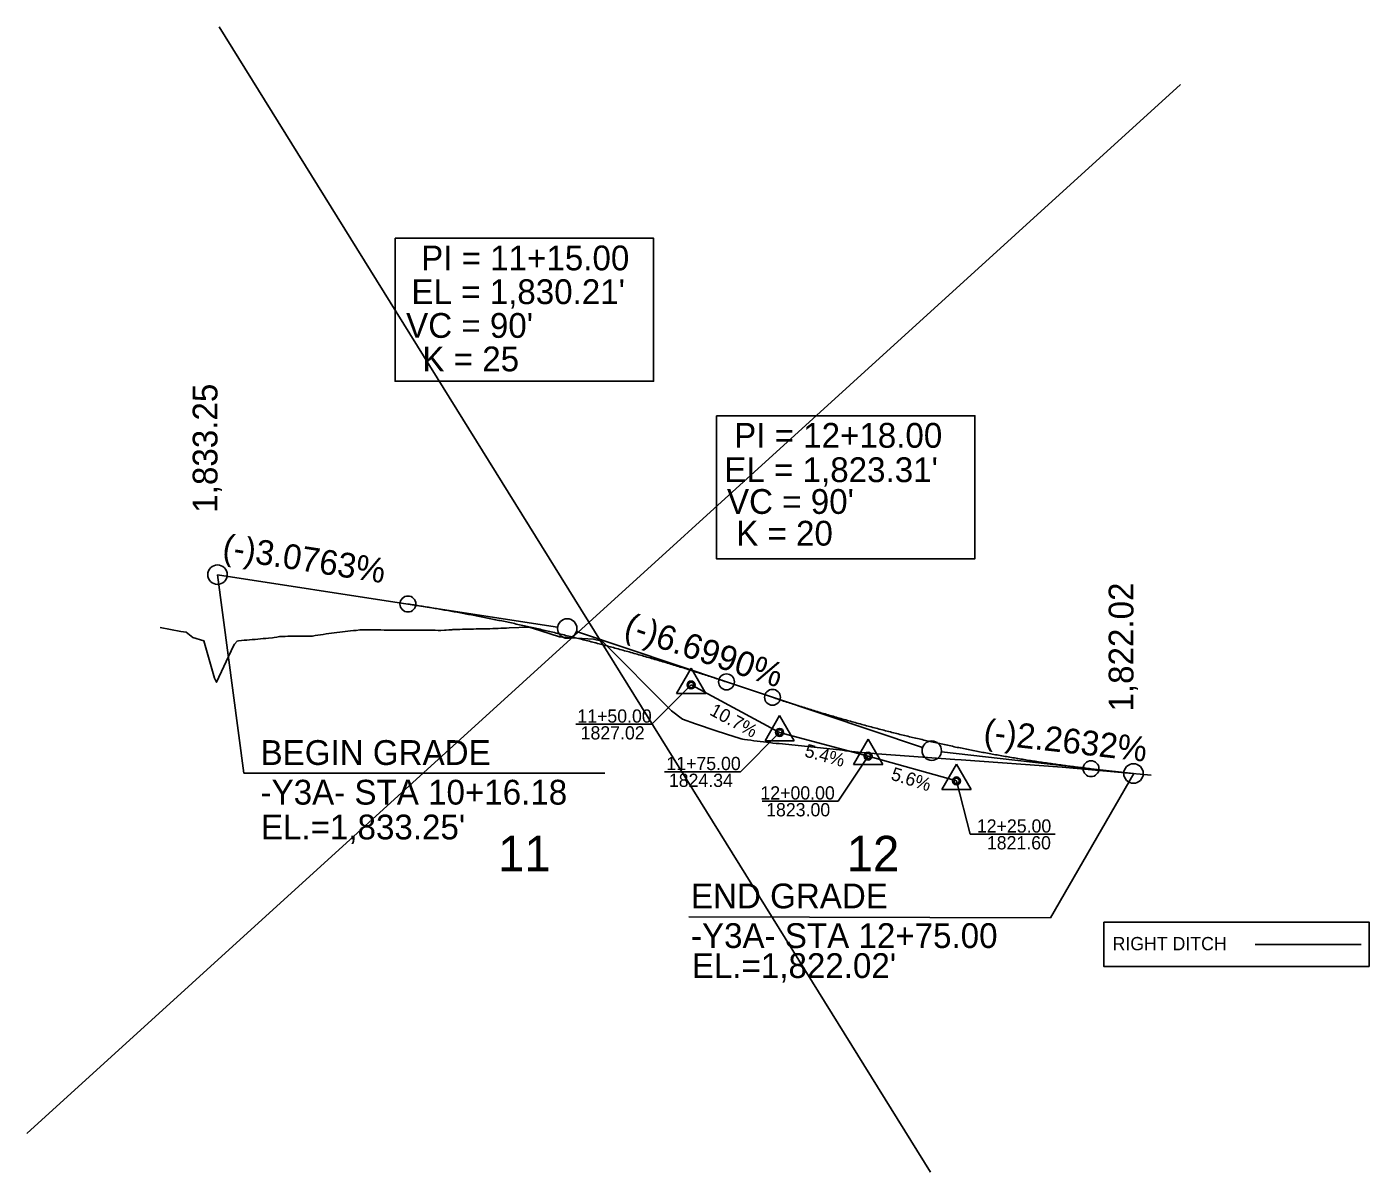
# Model space of a CAD drawing. Extents: x 557032 to 558930, y 525869 to 527437.
# Drawn here: x 557603.4 to 557982.7, y 527113.6 to 527437.1 of the extents above; entities that cross this region are included whole.
import ezdxf

# ---------------------------------------------------------------- set-up
doc = ezdxf.new("R2010")
doc.units = 0
for name, color, linetype in [('Exist Vertical Profile Ground Line', 7, 'Continuous'), ('Exist Vertical Profile Horizontal Axis Label Major', 7, 'Continuous'), ('Prop Grid Mask', 7, 'Continuous'), ('Prop PFL Ditch Label CELL', 7, 'Continuous'), ('Prop PFL VPI Symbol CELL', 7, 'Continuous'), ('Prop Vertical Profile Curve Label', 7, 'Continuous'), ('Prop Vertical Profile Grade', 7, 'Continuous'), ('Prop Vertical Profile Grade Label', 7, 'Continuous'), ('Prop VPI Label', 7, 'Continuous')]:
    doc.layers.add(name, color=color, linetype=linetype)

msp = doc.modelspace()

# ---------------------------------------------------------------- linework, layer by layer
at = {"layer": 'Exist Vertical Profile Ground Line'}
for points in [[(557641.09, 527267.42), (557646.95, 527266.33), (557648.42, 527266.09), (557650.28, 527264.59), (557653.44, 527263.67), (557656.4, 527253.1), (557657.02, 527251.96), (557661.78, 527262.29), (557662.12, 527262.74), (557662.81, 527263.59), (557663.24, 527263.64), (557664.01, 527263.73), (557664.79, 527263.8), (557665.56, 527263.87), (557666.33, 527263.94), (557667.1, 527264.01), (557667.87, 527264.08), (557668.65, 527264.15), (557669.42, 527264.21), (557670.19, 527264.28), (557670.96, 527264.34), (557671.73, 527264.4), (557672.77, 527264.48), (557673.28, 527264.57), (557674.05, 527264.7), (557674.82, 527264.84), (557675.2, 527264.9), (557675.59, 527264.91), (557676.36, 527264.92), (557677.14, 527264.93), (557677.91, 527264.94), (557678.68, 527264.94), (557679.45, 527264.95), (557680.22, 527264.96), (557681, 527264.97), (557681.4, 527264.97), (557681.77, 527264.97), (557682.54, 527264.96), (557683.31, 527264.96), (557683.62, 527264.96), (557684.08, 527264.99), (557684.85, 527265.16), (557685.63, 527265.27), (557686.4, 527265.38), (557687.17, 527265.48), (557687.94, 527265.59), (557688.71, 527265.69), (557689.49, 527265.79), (557690.26, 527265.89), (557691.03, 527265.99), (557691.8, 527266.08), (557692.57, 527266.18), (557693.35, 527266.27), (557694.12, 527266.36), (557694.89, 527266.45), (557695.66, 527266.54), (557696.43, 527266.62), (557697.49, 527266.74), (557697.98, 527266.74), (557698.75, 527266.74), (557699.52, 527266.73), (557700.29, 527266.73), (557701.06, 527266.73), (557701.84, 527266.72), (557702.61, 527266.72), (557703.38, 527266.72), (557704.4, 527266.71), (557704.92, 527266.71), (557705.7, 527266.71), (557706.47, 527266.71), (557707.24, 527266.71), (557708.01, 527266.71), (557708.78, 527266.71), (557709.55, 527266.7), (557710.33, 527266.7), (557711.1, 527266.7), (557711.87, 527266.7), (557712.64, 527266.69), (557713.41, 527266.69), (557714.19, 527266.69), (557714.96, 527266.68), (557715.73, 527266.68), (557716.5, 527266.68), (557717.27, 527266.67), (557718.05, 527266.67), (557718.51, 527266.66), (557718.82, 527266.64), (557719.59, 527266.6), (557720.36, 527266.59), (557721.39, 527266.65), (557721.9, 527266.69), (557722.68, 527266.75), (557723.45, 527266.81), (557723.78, 527266.84), (557724.22, 527266.85), (557724.99, 527266.88), (557725.76, 527266.9), (557726.54, 527266.92), (557727.31, 527266.94), (557728.08, 527266.96), (557728.85, 527266.98)], [(557728.85, 527266.98), (557729.62, 527267), (557730.39, 527267.02), (557731.17, 527267.03), (557731.94, 527267.05), (557732.71, 527267.06), (557733.48, 527267.08), (557734.25, 527267.09), (557735.04, 527267.1), (557735.8, 527267.13), (557736.57, 527267.17), (557737.34, 527267.2), (557738.11, 527267.24), (557738.89, 527267.27), (557739.66, 527267.3), (557745.22, 527267.52), (557745.9, 527267.35), (557746.29, 527267.24), (557753.92, 527264.77), (557757.25, 527264.47), (557763.56, 527264.17), (557765.51, 527263.7), (557765.84, 527263.67), (557785.59, 527243.9), (557788.71, 527241.52), (557792.33, 527240.19), (557798.13, 527238.24), (557799.02, 527237.94), (557799.92, 527237.64), (557800.81, 527237.36), (557801.7, 527237.07), (557802.6, 527236.79), (557803.49, 527236.52), (557804.39, 527236.26), (557805.28, 527235.99), (557805.71, 527235.87), (557806.17, 527235.81), (557807.07, 527235.69), (557807.96, 527235.58), (557808.85, 527235.46), (557809.75, 527235.35), (557810.64, 527235.24), (557811.53, 527235.12), (557812.43, 527235.01), (557813.32, 527234.9), (557814.21, 527234.79), (557815.11, 527234.71), (557816, 527234.63), (557816.89, 527234.54), (557817.79, 527234.46), (557818.68, 527234.38), (557819.57, 527234.29), (557820.47, 527234.21), (557821.36, 527234.12), (557822.26, 527234.03), (557823.15, 527233.93), (557824.04, 527233.83), (557824.94, 527233.73), (557825.83, 527233.63), (557826.72, 527233.53), (557827.62, 527233.44), (557828.51, 527233.34), (557829.4, 527233.24), (557830.3, 527233.14), (557831.19, 527233.04), (557832.08, 527232.94), (557832.98, 527232.84), (557833.87, 527232.74), (557834.76, 527232.64), (557835.66, 527232.54), (557836.55, 527232.44), (557837.45, 527232.34), (557838.34, 527232.24), (557839.23, 527232.14), (557840.13, 527232.04), (557840.56, 527231.99), (557841.02, 527231.96), (557841.91, 527231.9), (557842.81, 527231.84), (557843.7, 527231.77), (557865.63, 527230.19), (557867.43, 527230.07), (557895.94, 527227.95), (557921.09, 527225.74)]]:
    msp.add_lwpolyline(points, dxfattribs=at)
at = {"layer": 'Prop Grid Mask'}
msp.add_lwpolyline([(557907.68, 527184.23), (557982.68, 527184.23), (557982.68, 527171.73), (557907.68, 527171.73)], close=True, dxfattribs=at)
at = {"layer": 'Prop PFL Ditch Label CELL'}
for p, q in [((557791.09, 527251.19), (557780.04, 527240.08)), ((557791.09, 527251.19), (557816.09, 527237.79)), ((557780.04, 527240.08), (557758.55, 527240.08)), ((557816.09, 527237.79), (557805.04, 527226.68)), ((557816.09, 527237.79), (557841.09, 527231.09)), ((557841.09, 527231.09), (557832.66, 527218.37)), ((557841.09, 527231.09), (557866.09, 527224.09)), ((557805.04, 527226.68), (557783.55, 527226.68)), ((557866.09, 527224.09), (557869.91, 527209.04)), ((557832.66, 527218.37), (557811.17, 527218.37)), ((557893.99, 527209.04), (557869.91, 527209.04)), ((557907.68, 527176.73), (557907.68, 527176.73)), ((557950.46, 527177.9), (557980.46, 527177.9))]:
    msp.add_line(p, q, dxfattribs=at)
at = {"layer": 'Prop PFL VPI Symbol CELL'}
for p, q in [((557791.09, 527255.96), (557786.98, 527248.82)), ((557791.09, 527255.96), (557795.23, 527248.82)), ((557786.98, 527248.82), (557795.23, 527248.82)), ((557816.09, 527242.56), (557811.98, 527235.42)), ((557816.09, 527242.56), (557820.23, 527235.42)), ((557841.09, 527235.86), (557836.98, 527228.72)), ((557841.09, 527235.86), (557845.23, 527228.72)), ((557811.98, 527235.42), (557820.23, 527235.42)), ((557836.98, 527228.72), (557845.23, 527228.72)), ((557866.09, 527228.86), (557861.98, 527221.72)), ((557866.09, 527228.86), (557870.23, 527221.72)), ((557861.98, 527221.72), (557870.23, 527221.72))]:
    msp.add_line(p, q, dxfattribs=at)
for centre, radius in [((557791.09, 527251.19), 1.12), ((557791.09, 527251.19), 0.765), ((557816.09, 527237.79), 1.12), ((557816.09, 527237.79), 0.765), ((557841.09, 527231.09), 1.12), ((557841.09, 527231.09), 0.765), ((557866.09, 527224.09), 1.12), ((557866.09, 527224.09), 0.765)]:
    msp.add_circle(centre, radius, dxfattribs=at)
at = {"layer": 'Prop Vertical Profile Curve Label'}
for points in [[(557707.45, 527377.35), (557780.51, 527377.35), (557780.51, 527336.95), (557707.45, 527336.95)], [(557798.23, 527327.23), (557871.29, 527327.23), (557871.29, 527286.83), (557798.23, 527286.83)]]:
    msp.add_lwpolyline(points, close=True, dxfattribs=at)
for centre in [(557711.09, 527274.06), (557801.09, 527252.07), (557814.09, 527247.71), (557904.09, 527227.55)]:
    msp.add_circle(centre, 2.25, dxfattribs=at)
at = {"layer": 'Prop Vertical Profile Grade'}
for p, q in [((557657.27, 527282.34), (557711.09, 527274.06)), ((557801.09, 527252.07), (557814.09, 527247.71)), ((557904.09, 527227.55), (557916.09, 527226.19))]:
    msp.add_line(p, q, dxfattribs=at)
for points in [[(557711.09, 527274.06), (557712.89, 527273.78), (557714.69, 527273.49), (557716.49, 527273.2), (557718.29, 527272.9), (557720.09, 527272.59), (557721.89, 527272.28), (557723.69, 527271.96), (557725.49, 527271.64), (557727.29, 527271.3), (557729.09, 527270.97), (557730.89, 527270.62), (557732.69, 527270.27), (557734.49, 527269.91), (557736.29, 527269.54), (557738.09, 527269.17), (557739.89, 527268.8), (557741.69, 527268.41), (557743.49, 527268.02), (557745.29, 527267.62), (557747.09, 527267.22), (557748.89, 527266.81), (557750.69, 527266.39), (557752.49, 527265.97), (557754.29, 527265.54), (557756.09, 527265.1), (557757.89, 527264.66), (557759.69, 527264.21), (557761.49, 527263.75), (557763.29, 527263.29), (557765.09, 527262.82), (557766.89, 527262.34), (557768.69, 527261.86), (557770.49, 527261.37), (557772.29, 527260.88), (557774.09, 527260.38), (557775.89, 527259.87), (557777.69, 527259.35), (557779.49, 527258.83), (557781.29, 527258.3), (557783.09, 527257.77), (557784.89, 527257.23), (557786.69, 527256.68), (557788.49, 527256.13), (557790.29, 527255.57), (557792.09, 527255), (557793.89, 527254.42), (557795.69, 527253.84), (557797.49, 527253.26), (557799.29, 527252.67), (557801.09, 527252.07)], [(557814.09, 527247.71), (557815.89, 527247.11), (557817.69, 527246.52), (557819.49, 527245.94), (557821.29, 527245.36), (557823.09, 527244.8), (557824.89, 527244.24), (557826.69, 527243.69), (557828.49, 527243.14), (557830.29, 527242.61), (557832.09, 527242.08), (557833.89, 527241.56), (557835.69, 527241.05), (557837.49, 527240.55), (557839.29, 527240.05), (557841.09, 527239.57), (557842.89, 527239.09), (557844.69, 527238.62), (557846.49, 527238.15), (557848.29, 527237.7), (557850.09, 527237.25), (557851.89, 527236.81), (557853.69, 527236.38), (557855.49, 527235.96), (557857.29, 527235.54), (557859.09, 527235.13), (557860.89, 527234.73), (557862.69, 527234.34), (557864.49, 527233.96), (557866.29, 527233.58), (557868.09, 527233.22), (557869.89, 527232.86), (557871.69, 527232.51), (557873.49, 527232.16), (557875.29, 527231.83), (557877.09, 527231.5), (557878.89, 527231.18), (557880.69, 527230.87), (557882.49, 527230.57), (557884.29, 527230.27), (557886.09, 527229.98), (557887.89, 527229.7), (557889.69, 527229.43), (557891.49, 527229.17), (557893.29, 527228.91), (557895.09, 527228.66), (557896.89, 527228.42), (557898.69, 527228.19), (557900.49, 527227.97), (557902.29, 527227.75), (557904.09, 527227.55)]]:
    msp.add_spline(points, degree=3, dxfattribs=at)
at = {"layer": 'Prop VPI Label'}
for p, q in [((557858.73, 527113.61), (557657.73, 527437.05)), ((557603.4, 527124.48), (557929.35, 527420.74)), ((557664.72, 527226.24), (557657.27, 527282.34)), ((557711.09, 527274.06), (557753.38, 527267.56)), ((557801.09, 527252.07), (557758.7, 527266.26)), ((557814.09, 527247.71), (557856.49, 527233.51)), ((557904.09, 527227.55), (557861.83, 527232.33)), ((557766.76, 527226.24), (557664.72, 527226.24)), ((557892.67, 527185.43), (557916.18, 527226.18)), ((557790.46, 527185.76), (557892.67, 527185.43))]:
    msp.add_line(p, q, dxfattribs=at)
for points in [[(557707.45, 527377.35), (557780.51, 527377.35), (557780.51, 527336.95), (557707.45, 527336.95)], [(557798.23, 527327.23), (557871.29, 527327.23), (557871.29, 527286.83), (557798.23, 527286.83)], [(557907.68, 527184.23), (557982.68, 527184.23), (557982.68, 527171.73), (557907.68, 527171.73)]]:
    msp.add_lwpolyline(points, close=True, dxfattribs=at)
for centre in [(557657.27, 527282.34), (557657.27, 527282.34), (557756.09, 527267.14), (557859.09, 527232.64), (557916.09, 527226.19), (557916.09, 527226.19)]:
    msp.add_circle(centre, 2.75, dxfattribs=at)

# ---------------------------------------------------------------- texts
at = {"layer": 'Exist Vertical Profile Horizontal Axis Label Major'}
for s, p in [('11', (557736.52, 527198.59)), ('12', (557835.06, 527198.59))]:
    msp.add_text(s, height=10, dxfattribs=at).set_placement(p)
at = {"layer": 'Prop PFL Ditch Label CELL'}
for s, height, p in [('11+50.00', 3.743, (557758.95, 527240.55)), ('1827.02', 3.743, (557759.88, 527235.8)), ('11+75.00', 3.743, (557784.1, 527227.15)), ('1824.34', 3.743, (557784.81, 527222.4)), ('12+00.00', 3.743, (557810.68, 527218.84)), ('1823.00', 3.743, (557812.3, 527214.09)), ('12+25.00', 3.743, (557871.84, 527209.5)), ('1821.60', 3.743, (557874.67, 527204.76)), ('RIGHT DITCH', 3.7425, (557910.18, 527176.28))]:
    msp.add_text(s, height=height, dxfattribs=at).set_placement(p)
for s, height, rotation, p in [('10.7%', 3.742, 331.5304, (557796.06, 527242.92)), ('5.4%', 3.742, 344.5312, (557822.92, 527231.04)), ('5.6%', 3.743, 342.5321, (557847.3, 527224.52))]:
    msp.add_text(s, height=height, rotation=rotation, dxfattribs=at).set_placement(p)
at = {"layer": 'Prop Vertical Profile Curve Label'}
for s, p in [("VC = 90'", (557710.57, 527349.23)), ('K = 25', (557715.17, 527339.77)), ("VC = 90'", (557801.23, 527299.51)), ('K = 20', (557803.83, 527290.55))]:
    msp.add_text(s, height=7, dxfattribs=at).set_placement(p)
at = {"layer": 'Prop Vertical Profile Grade Label'}
for s, rotation, p in [('(-)3.0763%', 351.2556, (557658.38, 527286.94)), ('(-)6.6990%', 341.4817, (557771.72, 527265.07)), ('(-)2.2632%', 353.544, (557873.5, 527234.69))]:
    msp.add_text(s, height=7, rotation=rotation, dxfattribs=at).set_placement(p)
at = {"layer": 'Prop VPI Label'}
for s, p in [('PI = 11+15.00', (557714.82, 527368.29)), ("EL = 1,830.21'", (557712.07, 527358.76)), ('PI = 12+18.00', (557803.25, 527318.19)), ("EL = 1,823.31'", (557800.49, 527308.48))]:
    msp.add_text(s, height=7, dxfattribs=at).set_placement(p)
for s, rotation, p in [('1,833.25', 90, (557657.27, 527299.84)), ('1,822.02', 90, (557916.09, 527243.69)), ('BEGIN GRADE', 360, (557669.44, 527228.61)), ('-Y3A- STA 10+16.18', 360, (557669.44, 527217.41)), ("EL.=1,833.25'", 360, (557669.52, 527207.58)), ('END GRADE', 360, (557791.05, 527188.11)), ('-Y3A- STA 12+75.00', 360, (557791.05, 527176.91)), ("EL.=1,822.02'", 360, (557791.29, 527168.44))]:
    msp.add_text(s, height=7, rotation=rotation, dxfattribs=at).set_placement(p)

doc.saveas('drawing.dxf')
